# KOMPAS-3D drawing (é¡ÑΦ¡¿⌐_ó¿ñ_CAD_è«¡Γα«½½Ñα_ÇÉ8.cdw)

Views: Спереди 1, Проекционный вид 2, Проекционный вид 3, Проекционный вид 4, Проекционный вид 5, Проекционный вид 6, Спереди 7, Спереди, Проекционный вид 8, Проекционный вид 9, Проекционный вид 10, Проекционный вид 11, Проекционный вид 12, Спереди 13, Проекционный вид 14, Проекционный вид 15, Проекционный вид 16, Проекционный вид 17, Проекционный вид 18
Referenced files in D:\Рабочая папка\Новое\KSB_Наш_Контроллер\ВЫХОД\КД\11032019_Комплект_КД_с_моделями\КНМБ_424318_050_КД\: Технологическая_сборка_АР8_v2_0.t3d
Referenced files in D:\Рабочая папка\Новое\KSB_Наш_Контроллер\ВЫХОД\КД\11032019_Комплект_КД_с_моделями\Исходные данные\KSB\: Board.m3d, SO18.m3d, DD7.a3d, SOT-23.m3d, VT7.a3d, CE050M0220REG-1010.m3d, C16.a3d, 2EDGRС-5.0-03P-14.m3d, XS8.a3d, XS9.a3d, 2EDGRС-5.0-02P-14.m3d, XS5.a3d, XS2.a3d, XS13.a3d, XS12.a3d, 2EDGRС-5.0-04P-14.m3d, XS11.a3d, XS10.a3d, SRU5028.m3d, L2.a3d, EDR101A.m3d, K1.a3d, DS1092-12-N8S.m3d, GB1.a3d, C-TYPE_A.m3d, C18.a3d, C17.a3d, Extruded.m3d, 981821032.a3d, Extruded_1.m3d, 981821168.a3d, C11.a3d, C9.a3d, C5.a3d, Extruded_2.m3d, 981821304.a3d, Extruded_3.m3d, 981821440.a3d, C4.a3d, User_Library-IDC-14MS_Pin_1_____________.m3d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
Referenced files in D:\Рабочая папка\Новое\KSB_Наш_Контроллер\ВЫХОД\КД\11032019_Комплект_КД_с_моделями\Исходные данные\Винты гайки шайбы\: Стойка_11мм_М3.m3d, Шайба_М3_DIN125.m3d, Шайба_гроверная_М3_DIN127.m3d, Винт_М3х6_DIN7985.m3d, Саморез_М2,5х6.m3d
Referenced files in D:\Рабочая папка\Новое\KSB_Наш_Контроллер\ВЫХОД\КД\11032019_Комплект_КД_с_моделями\Исходные данные\Батарейка\: CR1220.m3d
Referenced files in D:\Рабочая папка\Новое\KSB_Наш_Контроллер\ВЫХОД\КД\11032019_Комплект_КД_с_моделями\Исходные данные\OrangePI\: Orange-pi-one-board.m3d, inductance.m3d, MicroUSB-B_Molex_105017-0001.m3d, hdmi.m3d, User Library-RMS-001L-08A0-GY_SignalPin.m3d, User Library-RMS-001L-08A0-GY_MechPin.m3d, User Library-RMS-001L-08A0-GY_LEDpin.m3d, User Library-RMS-001L-08A0-GY_CasePin.m3d, User Library-RMS-001L-08A0-GY_body.m3d, User Library-RMS-001L-08A0-GY.a3d, Allwinner-H3.m3d, PLS-1.m3d, USB_Defaut.m3d, MEM2055-00-190-01-A_revG.m3d, PLD-40.m3d, power-connector.m3d, SAMSUNG.m3d, Pushbutton - dik.m3d, Orange-pi-one.a3d
Referenced files in D:\Рабочая папка\Новое\KSB_Наш_Контроллер\ВЫХОД\КД\11032019_Комплект_КД_с_моделями\Исходные данные\microSD_card\micro-sd-slot-with-sd-card.snapshot.2 (1)\: sd.m3d
Referenced files in D:\Рабочая папка\Новое\KSB_Наш_Контроллер\ВЫХОД\КД\11032019_Комплект_КД_с_моделями\Исходные данные\Корпус\: Корпус_низ.m3d, Корпус_верх.m3d
Referenced files in D:\Рабочая папка\Новое\KSB_Наш_Контроллер\ВЫХОД\КД\11032019_Комплект_КД_с_моделями\Исходные данные\Клеммы\2\: 2EGDK-5.08-02P.m3d
Referenced files in D:\Рабочая папка\Новое\KSB_Наш_Контроллер\ВЫХОД\КД\11032019_Комплект_КД_с_моделями\Исходные данные\Клеммы\3\: 2EGDK-5.08-03P.m3d
Referenced files in D:\Рабочая папка\Новое\KSB_Наш_Контроллер\ВЫХОД\КД\11032019_Комплект_КД_с_моделями\Исходные данные\Клеммы\5\: 2EGDK-5.08-05P.m3d
Referenced files in D:\Рабочая папка\Новое\KSB_Наш_Контроллер\ВЫХОД\КД\11032019_Комплект_КД_с_моделями\Исходные данные\Клеммы\4\: 2EGDK-5.08-04P.m3d
Referenced files in D:\Рабочая папка\Новое\KSB_Наш_Контроллер\ВЫХОД\КД\11032019_Комплект_КД_с_моделями\Исходные данные\Клеммы\9\: 2EGDK-5.08-09P.a3d
Referenced files in D:\Рабочая папка\Новое\KSB_Наш_Контроллер\ВЫХОД\КД\11032019_Комплект_КД_с_моделями\Исходные данные\SMA\: Sma female connector.m3d, Nuts etc_Shayba.m3d, Nuts etc_Grover.m3d, Nuts etc_Gayka.m3d
Referenced files in D:\Рабочая папка\Новое\KSB_Наш_Контроллер\ВЫХОД\КД\11032019_Комплект_КД_с_моделями\Исходные данные\SMA_antena\sma-antenna\: GSM_ANT_RA_SMA.m3d, GSM_ANT_WHIP.m3d, GSM_ANTENNA_900MHZ.a3d
Referenced files in D:\Рабочая папка\Новое\KSB_Наш_Контроллер\ВЫХОД\КД\11032019_Комплект_КД_с_моделями\Исходные данные\Модем_SIM800L\: Модем_SIM800L_V2.0_плата.m3d, CircuitWorks-HEADER 2_54 VERTICAL 5X.m3d, CircuitWorks-HEADER 2_54 VERTICAL 2X.m3d, Модем_SIM800L.a3d
Referenced files in D:\Рабочая папка\Новое\KSB_Наш_Контроллер\ВЫХОД\КД\11032019_Комплект_КД_с_моделями\Исходные данные\Радиомодем433\: Радиомодем433_HC11_HC12.m3d, CircuitWorks-HEADER 2_54 VERTICAL 5X.m3d, Радиомодем433_со_штырьками_сборка.a3d
Referenced files in D:\Рабочая папка\Новое\KSB_Наш_Контроллер\ВЫХОД\КД\11032019_Комплект_КД_с_моделями\Исходные данные\Этикетки\: Этикетка_лицевая.m3d, Маркировка_шильдик.m3d, Маркировка_Верх.m3d, Маркировка_Низ.m3d, Маркировка_ANT.m3d, Маркировка_HDMI_USB2.m3d, Гарантийная_пломба_microSD.m3d, Маркировка_ОТК.m3d
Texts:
  Buhalov
  Чертеж 1. Чертеж общего вида контроллера с антенной радиомодуля и разъемами
  Чертеж 2. Чертеж общего вида контроллера без антенны и разъема антенны
  Граница
  Контроллер АР8
  Схемы  подключений
  Бухалов
  Горбунов
  Якимов
  Андреев
  ООО "НПО"Каскад-ГРУП"
  Без основной надписи.
  Board
  SO18
  DD7
  SOT-23
  VT7
  CE050M0220REG-1010
  XS8
  XS9
  XS5
  XS2
  XS13
  XS12
  XS11
  XS10
  SRU5028
  EDR101A
  DS1092-12-N8S
  GB1
  C-TYPE_A
  Extruded
  User_Library-IDC-14MS_Pin_1_____________
  User_Library-IDC-14MS_Case_IDC-14MS_____________
  IDC-14MS
  XP2
  VT1
  SMB
  VD8
  MiniMELF_SOD-80
  VD3
  DA4
  PLS-3R
  XP1
  PBS-5_(DS-1023_-1x5)
  XS7
  MF-MSMF
  FU5
  FU4
  FU3
  FU2
  DS1040
  SA1
  SIP4(stand)
  TO263-5-1
  DA1
  SO16
  DA2
  DA3
  DD2
  DD3
  DD4
  DD5
  DD6
  Jumper
  SRP1265A
  DD1
  VT3
  Поверхности
  VD2
  L-934GD_G
  VD4
  VD6
  VD9
  VD10
  VD11
  VD12
  VD13
  VD14
  VD15
  VD16
  VD17
  VT2
  VT4
  VT5
  VT6
  VT8
  VT10
  VT11
  VT12
  DRB-9MA
  XP3
  PBS-7_(DS1023-1x7)
  XS4
  PBS-3_(DS-1023_-_1x3)
  XS3
  VD1
  VD7
  PBD-40_(DS1023-2X20)
  XS1
  HF41F
  VD18
  VD19
  VD20
  L-934YD
  VD5
  MF-R135
  FU1
  XS6
  VT9
  Плата KSB rev 2.0
  KSB rev. 2.0
  Стойка М3 11 мм
  Стойка М3 L=11мм
  Батарейка CR1220
  Шайба М3
  Шайба гроверная М3
  Винт М3х6
  Orange-pi-one-board
  inductance
  MicroUSB-B_Molex_105017-0001
  hdmi
  User Library-RMS-001L-08A0-GY_SignalPin
  User Library-RMS-001L-08A0-GY_MechPin
  User Library-RMS-001L-08A0-GY_LEDpin
  User Library-RMS-001L-08A0-GY_CasePin
  User Library-RMS-001L-08A0-GY_body
  User Library-RMS-001L-08A0-GY
  Allwinner-H3
  PLS-1
  MEM2055-00-190-01-A_revG
  PLD-40
  power-connector
  SAMSUNG
  Pushbutton - dik
  Микрокомпьютер Orange Pi One
  Micro SD карта
  Mocro SD карта
  Корпус(основание)
  SANHE 23-66A (основание)
  Корпус(крышка)
  SANHE 23-66A (крышка)
  SMA разъем
  SMA разъем на корпус
  SMA шайба стопорная
  SMA гроверная шайба
  SMA гайка
  Антенна GSM/433МГц
  CircuitWorks-HEADER 2_54 VERTICAL 5X
  CircuitWorks-HEADER 2_54 VERTICAL 2X
  Модем SIM800L V2.0
  Саморез М2,5х6
  Радиомодем 433Мгц
  Этикетка лицевая
  Шильдик
  Маркировка верх
  Маркировка низ
  Маркировка SMA
  Маркировка HDMI_USB2
  Гарантийная пломба
  Этикетка ОТК
  Контроллер АР-8
  КНМБ.424318.050
  Сборочный вид
Dimensions and other numbers on the sheet: 1:1; 1; 4; 2EDGRС-5.0-03P-14; 2EDGRС-5.0-02P-14; 2EDGRС-5.0-04P-14; 8SO-EP; 2EDGRС-5.0-09P-14; 2EGDK-5.0-02P; 2EGDK-5.0-03P; 2EGDK-5.08-05P; 2EGDK-5.08-04P; 2EGDK-5.0-09P; 2EGDK-5.0-04P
